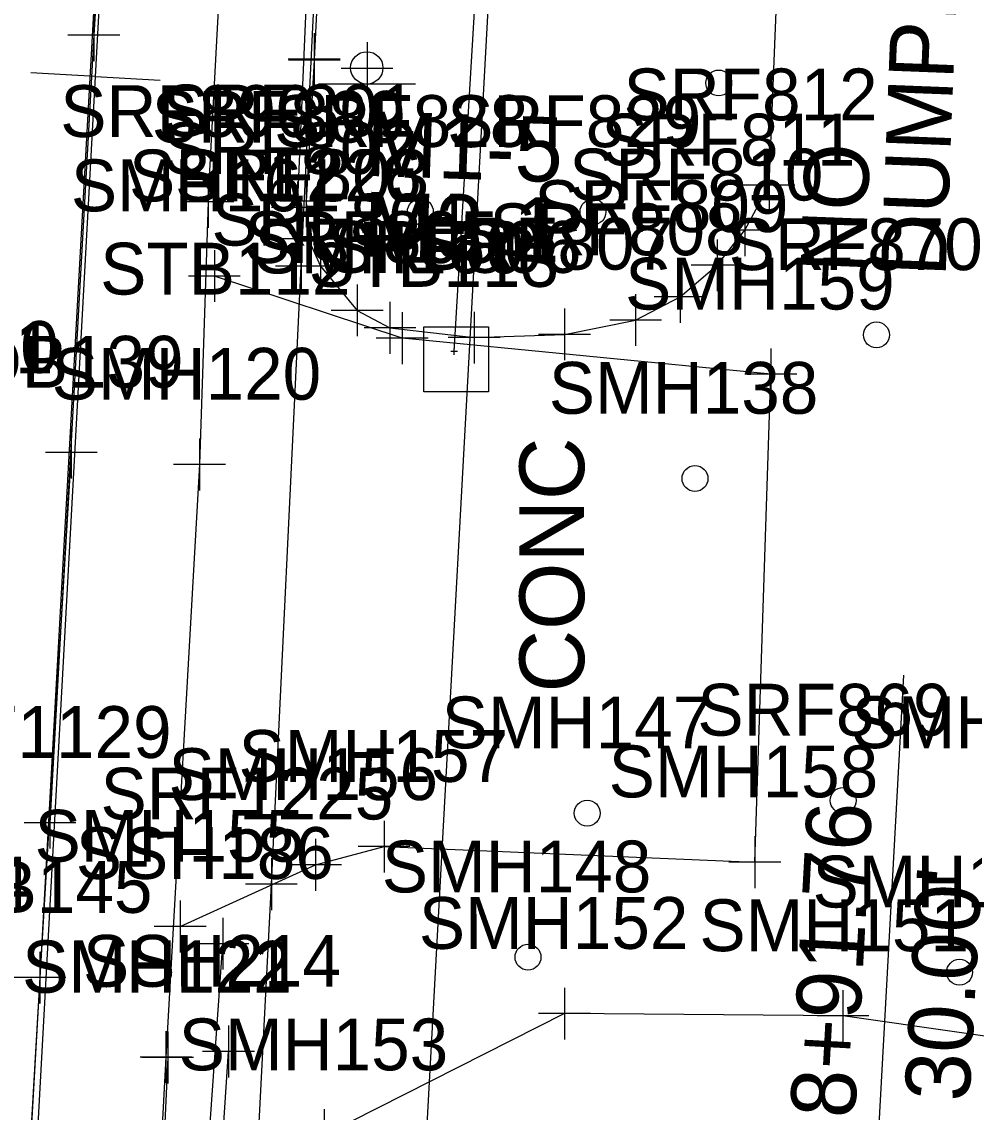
# Model space of a CAD drawing. Extents: x 941041 to 969446, y 397014 to 416764.
# Drawn here: x 951896.1 to 951969.6, y 403746.1 to 403830.3 of the extents above; entities that cross this region are included whole.
import ezdxf

# ---------------------------------------------------------------- set-up
doc = ezdxf.new("R2010")
doc.units = 0
for name, color, linetype in [('SURVEY - CENTERLINE - Preliminary', 7, 'Continuous'), ('SURVEY - CENTERLINE - Preliminary Curve Text', 7, 'Continuous'), ('SURVEY - DRAINAGE - Area Shapes', 7, 'Continuous'), ('SURVEY - DRAINAGE - Pipes and Culverts', 7, 'Continuous'), ('SURVEY - DRAINAGE - Pipes and Culverts - Points - Locators', 7, 'Continuous'), ('SURVEY - DRAINAGE - Pipes and Culverts - Points - Numbers', 7, 'Continuous'), ('SURVEY - DRAINAGE - Storm Sewer', 7, 'Continuous'), ('SURVEY - DRAINAGE - Storm Sewer - Points - Numbers', 7, 'Continuous'), ('SURVEY - DTM - Breaklines', 7, 'Continuous'), ('SURVEY - DTM - Breaklines - Points - Locators', 7, 'Continuous'), ('SURVEY - DTM - Breaklines - Points - Numbers', 7, 'Continuous'), ('SURVEY - DTM - Spot Points - Locators', 7, 'Continuous'), ('SURVEY - DTM - Spot Points - Point Numbers', 7, 'Continuous'), ('SURVEY - PROPERTY - ROW Lines', 7, 'Continuous'), ('SURVEY - PROPERTY - Station and Offset Flags', 7, 'Continuous'), ('SURVEY - ROADSIDE BARRIERS - Points - Locators', 7, 'Continuous'), ('SURVEY - ROADSIDE BARRIERS - Points - Numbers', 7, 'Continuous'), ('SURVEY - ROADSIDE BARRIERS with Text', 7, 'Continuous'), ('SURVEY - TRAFFIC CONTROL - Signs - Points - Locators', 7, 'Continuous'), ('SURVEY - TRAFFIC CONTROL - Signs and Devices with Text', 7, 'Continuous'), ('SURVEY - TRANSPORTATION - Features', 7, 'Continuous'), ('SURVEY - TRANSPORTATION - Features - Points - Locators', 7, 'Continuous'), ('SURVEY - TRANSPORTATION - Features - Points - Numbers', 7, 'Continuous'), ('SURVEY - TRANSPORTATION - Features Text', 7, 'Continuous'), ('SURVEY - TRANSPORTATION - Roads', 7, 'Continuous'), ('SURVEY - TRANSPORTATION - Roads - Points - Locators', 7, 'Continuous'), ('SURVEY - TRANSPORTATION - Roads - Points - Numbers', 7, 'Continuous'), ('SURVEY - UTILITIES - Telephone (Underground) - Points - Locators', 7, 'Continuous'), ('SURVEY - UTILITIES - Telephone (Underground) - Points - Numbers', 7, 'Continuous'), ('SURVEY - UTILITIES - Telephone (Underground) with Text', 7, 'Continuous')]:
    doc.layers.add(name, color=color, linetype=linetype)

msp = doc.modelspace()

# ---------------------------------------------------------------- linework, layer by layer
at = {"layer": 'SURVEY - CENTERLINE - Preliminary'}
msp.add_line((951818.981, 402312.968), (951929.937, 404341.516), dxfattribs=at)
at = {"layer": 'SURVEY - CENTERLINE - Preliminary Curve Text'}
for q in [(951896.75, 403826.325), (951906.735, 403825.779)]:
    msp.add_line((951901.742, 403826.052), q, dxfattribs=at)
at = {"layer": 'SURVEY - DRAINAGE - Area Shapes'}
msp.add_lwpolyline([(951394.91, 403299.536), (951490.14, 404032.201), (951534.571, 404027.309), (951536.745, 404050.339), (951913.116, 404038.394), (951897.459, 403756.486), (951887.407, 403584.591), (951722.845, 403491.25), (951657.464, 403432.193), (951570.1, 403333.857)], dxfattribs=at)
at = {"layer": 'SURVEY - DRAINAGE - Pipes and Culverts'}
msp.add_lwpolyline([(951929.444, 403804.814), (951935.506, 403906.392), (951938.06, 403923.096)], dxfattribs=at)
at = {"layer": 'SURVEY - DRAINAGE - Pipes and Culverts - Points - Locators'}
for p, q in [((951929.694, 403804.814), (951929.194, 403804.814)), ((951929.444, 403804.564), (951929.444, 403805.064)), ((951929.444, 403804.814), (951929.444, 403804.814)), ((951929.444, 403804.814), (951929.444, 403804.814))]:
    msp.add_line(p, q, dxfattribs=at)
at = {"layer": 'SURVEY - DRAINAGE - Storm Sewer'}
msp.add_line((951929.588, 403804.218), (951929.588, 403804.218), dxfattribs=at)
msp.add_lwpolyline([(951927.088, 403801.718), (951927.088, 403806.718), (951932.088, 403806.718), (951932.088, 403801.718), (951927.088, 403801.718)], dxfattribs=at)
at = {"layer": 'SURVEY - DTM - Breaklines'}
for points in [[(951949.779, 404713.918), (951947.173, 404665.001), (951944.505, 404613.571), (951941.806, 404562.024), (951938.832, 404498.276), (951936.185, 404444.735), (951933.789, 404401.071), (951930.89, 404347.486), (951927.861, 404294.198), (951924.618, 404236.761), (951921.73, 404184.357), (951918.627, 404133.081), (951915.542, 404080.735), (951913.116, 404038.394), (951910.337, 403985.547), (951907.608, 403934.318), (951904.728, 403883.327), (951901.621, 403829.233), (951898.232, 403768.445)], [(951899.878, 403797.03), (951897.459, 403756.486), (951895.103, 403715.326), (951892.651, 403672.689), (951890.098, 403629.579), (951887.407, 403584.591), (951885.29, 403540.638), (951882.607, 403490.831), (951880.064, 403438.72), (951877.649, 403396.759)], [(952052.424, 403750.087), (951996.089, 403748.278), (951959.461, 403753.528), (951937.955, 403753.706), (951919.411, 403744.33), (951914.356, 403717.205), (951914.763, 403681.401), (951927.271, 403658.289), (951940.68, 403647.827), (951991.851, 403656.35), (952039.728, 403671.731), (952061.805, 403680.377), (952092.796, 403692.546)]]:
    msp.add_lwpolyline(points, dxfattribs=at)
at = {"layer": 'SURVEY - DTM - Breaklines - Points - Locators'}
for p, q in [((951901.621, 403831.233), (951901.621, 403827.233)), ((951903.621, 403829.233), (951899.621, 403829.233)), ((951899.878, 403799.03), (951899.878, 403795.03)), ((951901.878, 403797.03), (951897.878, 403797.03)), ((951898.232, 403770.445), (951898.232, 403766.445)), ((951900.232, 403768.445), (951896.232, 403768.445)), ((951897.459, 403758.486), (951897.459, 403754.486)), ((951899.459, 403756.486), (951895.459, 403756.486)), ((951937.955, 403755.706), (951937.955, 403751.706)), ((951959.461, 403755.528), (951959.461, 403751.528)), ((951939.955, 403753.706), (951935.955, 403753.706)), ((951961.461, 403753.528), (951957.461, 403753.528)), ((951919.411, 403746.33), (951919.411, 403742.33))]:
    msp.add_line(p, q, dxfattribs=at)
at = {"layer": 'SURVEY - DTM - Spot Points - Locators'}
for centre in [(951949.866, 403825.553), (951926.827, 403815.614), (951940.157, 403815.599), (951962.045, 403806.105), (951948.035, 403795.018), (951959.476, 403770.169), (951939.714, 403769.188), (951935.141, 403758.066), (951968.464, 403756.902)]:
    msp.add_circle(centre, 1, dxfattribs=at)
at = {"layer": 'SURVEY - PROPERTY - ROW Lines'}
msp.add_line((951925.786, 403716.337), (951959.892, 404339.877), dxfattribs=at)
at = {"layer": 'SURVEY - PROPERTY - Station and Offset Flags'}
msp.add_line((951964.123, 403779.827), (951962.04, 403741.748), dxfattribs=at)
at = {"layer": 'SURVEY - ROADSIDE BARRIERS - Points - Locators'}
for p, q in [((951911.576, 403761.105), (951911.576, 403757.105)), ((951913.576, 403759.105), (951909.576, 403759.105))]:
    msp.add_line(p, q, dxfattribs=at)
at = {"layer": 'SURVEY - ROADSIDE BARRIERS with Text'}
msp.add_lwpolyline([(952302.135, 403750.83), (952286.564, 403742.279), (952273.051, 403736.736), (952213.457, 403717.521), (952150.483, 403697.048), (952082.927, 403675.137), (952023.399, 403655.806), (951969.446, 403638.984), (951959.655, 403636.718), (951945.401, 403635.92), (951933.435, 403639.984), (951918.802, 403651.787), (951913.011, 403662.601), (951908.798, 403681.047), (951907.828, 403705.824), (951911.576, 403759.105)], dxfattribs=at)
at = {"layer": 'SURVEY - TRAFFIC CONTROL - Signs - Points - Locators'}
for p, q in [((951922.716, 403828.691), (951922.716, 403824.691)), ((951920.716, 403826.691), (951924.716, 403826.691))]:
    msp.add_line(p, q, dxfattribs=at)
at = {"layer": 'SURVEY - TRAFFIC CONTROL - Signs and Devices with Text'}
msp.add_line((951926.466, 403825.467), (951918.966, 403825.467), dxfattribs=at)
msp.add_circle((951922.695, 403826.716), 1.25, dxfattribs=at)
at = {"layer": 'SURVEY - TRANSPORTATION - Features'}
for points in [[(951920.104, 403856.703), (951918.636, 403827.397)], [(951918.637, 403827.303), (951918.002, 403816.42), (951918.176, 403813.52), (951919.129, 403811.418), (951921.946, 403808), (951924.48, 403806.652), (951930.989, 403805.895), (951937.957, 403806.145), (951943.454, 403807.253), (951946.881, 403809.044), (951949.735, 403811.48), (951951.889, 403814.181), (951953.756, 403817.669), (951955.143, 403852.178)], [(951908.281, 403760.436), (951918.73, 403765.195), (951924.029, 403766.597), (951952.657, 403765.405), (951953.895, 403803.062), (951925.422, 403805.854), (951910.929, 403810.646)], [(952398.443, 403784.202), (952342.678, 403764.131), (952306.797, 403754.238), (952300.473, 403753.951), (952294.735, 403748.804), (952274.378, 403738.859), (952197.478, 403713.287), (952143.022, 403695.934), (952121.499, 403689.539), (952063.685, 403670.647), (952006.844, 403652.208), (951952.436, 403637.983), (951939.416, 403639.207), (951926.692, 403646.99), (951915.446, 403661.398), (951909.299, 403684.874), (951909.408, 403711.073), (951912.018, 403750.78)]]:
    msp.add_lwpolyline(points, dxfattribs=at)
at = {"layer": 'SURVEY - TRANSPORTATION - Features - Points - Locators'}
for p, q in [((951918.636, 403829.397), (951918.636, 403825.397)), ((951918.637, 403829.303), (951918.637, 403825.303)), ((951920.636, 403827.397), (951916.636, 403827.397)), ((951920.637, 403827.303), (951916.637, 403827.303)), ((951953.756, 403819.669), (951953.756, 403815.669)), ((951918.002, 403818.42), (951918.002, 403814.42)), ((951955.756, 403817.669), (951951.756, 403817.669)), ((951920.002, 403816.42), (951916.002, 403816.42)), ((951918.176, 403815.52), (951918.176, 403811.52)), ((951951.889, 403816.181), (951951.889, 403812.181)), ((951953.889, 403814.181), (951949.889, 403814.181)), ((951920.176, 403813.52), (951916.176, 403813.52)), ((951919.129, 403813.418), (951919.129, 403809.418)), ((951949.735, 403813.48), (951949.735, 403809.48)), ((951910.929, 403812.646), (951910.929, 403808.646)), ((951921.129, 403811.418), (951917.129, 403811.418)), ((951951.735, 403811.48), (951947.735, 403811.48)), ((951912.929, 403810.646), (951908.929, 403810.646)), ((951946.881, 403811.044), (951946.881, 403807.044)), ((951921.946, 403810), (951921.946, 403806)), ((951943.454, 403809.253), (951943.454, 403805.253)), ((951948.881, 403809.044), (951944.881, 403809.044)), ((951923.946, 403808), (951919.946, 403808)), ((951924.48, 403808.652), (951924.48, 403804.652)), ((951937.957, 403808.145), (951937.957, 403804.145)), ((951925.422, 403807.854), (951925.422, 403803.854)), ((951930.989, 403807.895), (951930.989, 403803.895)), ((951945.454, 403807.253), (951941.454, 403807.253)), ((951926.48, 403806.652), (951922.48, 403806.652)), ((951927.422, 403805.854), (951923.422, 403805.854)), ((951932.989, 403805.895), (951928.989, 403805.895)), ((951939.957, 403806.145), (951935.957, 403806.145)), ((951953.895, 403805.062), (951953.895, 403801.062)), ((951955.895, 403803.062), (951951.895, 403803.062)), ((951924.029, 403768.597), (951924.029, 403764.597)), ((951918.73, 403767.195), (951918.73, 403763.195)), ((951952.657, 403767.405), (951952.657, 403763.405)), ((951926.029, 403766.597), (951922.029, 403766.597)), ((951920.73, 403765.195), (951916.73, 403765.195)), ((951954.657, 403765.405), (951950.657, 403765.405)), ((951908.281, 403762.436), (951908.281, 403758.436)), ((951910.281, 403760.436), (951906.281, 403760.436)), ((951912.018, 403752.78), (951912.018, 403748.78)), ((951914.018, 403750.78), (951910.018, 403750.78))]:
    msp.add_line(p, q, dxfattribs=at)
at = {"layer": 'SURVEY - TRANSPORTATION - Roads'}
for points in [[(951910.44, 403816.381), (951913.404, 403870.768), (951916.398, 403925.237), (951919.188, 403975.871), (951921.993, 404029.991), (951925.014, 404083.271), (951928.393, 404138.616), (951931.945, 404196.127), (951934.669, 404243.905), (951937.716, 404297.678), (951940.897, 404352.911), (951943.896, 404408.17), (951946.895, 404465.858), (951949.532, 404521.782), (951951.835, 404568.957), (951954.487, 404622.066), (951957.114, 404673.476), (951959.365, 404713.318)], [(951917.343, 403815.939), (951919.705, 403870.29), (951922.102, 403916.013), (951917.774, 403924.895), (951920.212, 403975.699), (951922.78, 404029.893), (951926.431, 404083.12), (951930.534, 404138.506), (951936.04, 404195.673), (951942.369, 404208.286), (951944.14, 404243.369), (951946.668, 404297.581), (951949.44, 404352.004), (951952.449, 404408.177), (951955.662, 404464.702), (951957.575, 404518.292), (951950.949, 404525.454)], [(951910.44, 403816.381), (951909.775, 403796.103), (951907.187, 403750.354), (951904.965, 403708.936), (951903.815, 403688.346), (951901.085, 403636.461), (951898.616, 403590.395), (951895.415, 403534.56), (951892.993, 403487.631), (951890.827, 403446.71), (951888.554, 403404.059), (951867.61, 403389.535)], [(951907.323, 403750.324), (951905.431, 403709.061), (951904.245, 403688.497)]]:
    msp.add_lwpolyline(points, dxfattribs=at)
at = {"layer": 'SURVEY - TRANSPORTATION - Roads - Points - Locators'}
for p, q in [((951910.44, 403818.381), (951910.44, 403814.381)), ((951917.343, 403817.939), (951917.343, 403813.939)), ((951912.44, 403816.381), (951908.44, 403816.381)), ((951919.343, 403815.939), (951915.343, 403815.939)), ((951909.775, 403798.103), (951909.775, 403794.103)), ((951911.775, 403796.103), (951907.775, 403796.103)), ((951907.187, 403752.354), (951907.187, 403748.354)), ((951907.323, 403752.324), (951907.323, 403748.324)), ((951909.187, 403750.354), (951905.187, 403750.354)), ((951909.323, 403750.324), (951905.323, 403750.324))]:
    msp.add_line(p, q, dxfattribs=at)
at = {"layer": 'SURVEY - UTILITIES - Telephone (Underground) - Points - Locators'}
for p, q in [((951917.638, 403813.409), (951917.638, 403809.409)), ((951919.638, 403811.409), (951915.638, 403811.409)), ((951915.328, 403765.696), (951915.328, 403761.696)), ((951917.328, 403763.696), (951913.328, 403763.696))]:
    msp.add_line(p, q, dxfattribs=at)
at = {"layer": 'SURVEY - UTILITIES - Telephone (Underground) with Text'}
msp.add_lwpolyline([(951921.072, 403252.511), (951917.249, 403313.567), (951917.074, 403357.955), (951918.669, 403383.166), (951923.504, 403409.874), (951922.998, 403472.254), (951917.445, 403500.161), (951911.149, 403531.608), (951914.776, 403569.296), (951914.968, 403577.099), (951921.593, 403637.923), (951914.392, 403680.006), (951913.219, 403722.898), (951915.328, 403763.696), (951917.638, 403811.409), (951920.116, 403862.527), (951924.086, 403909.79), (951927.508, 403936.004), (951928.781, 403988.584), (951930.827, 404027.449)], dxfattribs=at)

# ---------------------------------------------------------------- texts
at = {"layer": 'SURVEY - DRAINAGE - Pipes and Culverts - Points - Numbers'}
msp.add_text('STB113', height=4, dxfattribs=at).set_placement((951918.204, 403809.814))
at = {"layer": 'SURVEY - DRAINAGE - Storm Sewer - Points - Numbers'}
msp.add_text('STB112', height=4, dxfattribs=at).set_placement((951902.109, 403809.218))
at = {"layer": 'SURVEY - DTM - Breaklines - Points - Numbers'}
for s, p in [('SDB139', (951888.623, 403802.03)), ('SRF1129', (951885.025, 403773.445)), ('SDB145', (951886.219, 403761.486)), ('SMH152', (951926.715, 403758.706)), ('SMH151', (951948.379, 403758.528)), ('SMH153', (951908.171, 403749.33))]:
    msp.add_text(s, height=4, dxfattribs=at).set_placement(p)
at = {"layer": 'SURVEY - DTM - Spot Points - Point Numbers'}
for s, p in [('SRF828', (951915.54, 403820.614)), ('SRF829', (951928.902, 403820.599)), ('SRF870', (951950.632, 403811.105)), ('SMH138', (951936.748, 403800.018)), ('SRF869', (951948.221, 403775.169)), ('SMH147', (951928.474, 403774.188)), ('SMH145', (951960.103, 403774.2)), ('SMH148', (951923.854, 403763.066)), ('SMH146', (951957.114, 403761.902))]:
    msp.add_text(s, height=4, dxfattribs=at).set_placement(p)
at = {"layer": 'SURVEY - PROPERTY - Station and Offset Flags'}
for s, p in [('68+91.76', (951960.168, 403741.852)), ("30.00'", (951969.205, 403746.855))]:
    msp.add_text(s, height=5, rotation=86.86922, dxfattribs=at).set_placement(p)
at = {"layer": 'SURVEY - ROADSIDE BARRIERS - Points - Numbers'}
msp.add_text('SSH186', height=4, dxfattribs=at).set_placement((951900.226, 403764.105))
at = {"layer": 'SURVEY - TRAFFIC CONTROL - Signs and Devices with Text'}
for s, rotation, p in [('DUMPING', 87.77248, (951967.381, 403810.546)), ('M1-5', 358.1301, (951922.542, 403818.388)), ('NO', 87.77248, (951961.166, 403810.788)), ('M3-1', 358.1301, (951922.339, 403812.171))]:
    msp.add_text(s, height=5, rotation=rotation, dxfattribs=at).set_placement(p)
at = {"layer": 'SURVEY - TRANSPORTATION - Features - Points - Numbers'}
for s, p in [('SRF812', (951942.516, 403822.669)), ('SRF801', (951906.92, 403821.42)), ('SRF811', (951940.807, 403819.181)), ('SRF802', (951906.936, 403818.52)), ('SRF803', (951907.889, 403816.418)), ('SRF810', (951938.322, 403816.48)), ('SMH161', (951899.847, 403815.646)), ('SRF809', (951935.626, 403814.044)), ('SRF804', (951910.706, 403813)), ('SRF805', (951913.24, 403811.652)), ('SRF808', (951932.167, 403812.253)), ('SMH160', (951914.009, 403810.854)), ('SRF806', (951919.639, 403810.895)), ('SRF807', (951926.717, 403811.145)), ('SMH159', (951942.64, 403808.062)), ('SMH157', (951912.789, 403771.597)), ('SMH158', (951941.37, 403770.405)), ('SMH156', (951907.38, 403770.195)), ('SMH155', (951897.041, 403765.436)), ('SSH214', (951900.778, 403755.78))]:
    msp.add_text(s, height=4, dxfattribs=at).set_placement(p)
at = {"layer": 'SURVEY - TRANSPORTATION - Features Text'}
msp.add_text('CONC', height=4.998, rotation=90, dxfattribs=at).set_placement((951939.478, 403778.502))
at = {"layer": 'SURVEY - TRANSPORTATION - Roads - Points - Numbers'}
for s, p in [('SRF890', (951899.027, 403821.381)), ('SRF889', (951906.088, 403820.939)), ('SDB141', (951878.583, 403803.149)), ('SDB140', (951878.989, 403803.167)), ('SMH120', (951898.362, 403801.103)), ('SDB144', (951876.757, 403761.832)), ('SMH122', (951896.083, 403755.324)), ('SMH121', (951896.105, 403755.354))]:
    msp.add_text(s, height=4, dxfattribs=at).set_placement(p)
at = {"layer": 'SURVEY - UTILITIES - Telephone (Underground) - Points - Numbers'}
for s, p in [('SRF1226', (951904.336, 403816.409)), ('SRF1225', (951902.136, 403768.696))]:
    msp.add_text(s, height=4, dxfattribs=at).set_placement(p)

doc.saveas('drawing.dxf')
